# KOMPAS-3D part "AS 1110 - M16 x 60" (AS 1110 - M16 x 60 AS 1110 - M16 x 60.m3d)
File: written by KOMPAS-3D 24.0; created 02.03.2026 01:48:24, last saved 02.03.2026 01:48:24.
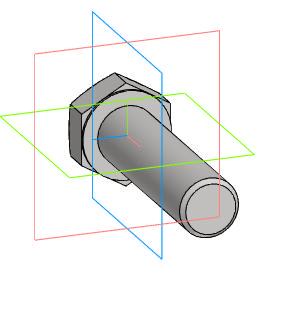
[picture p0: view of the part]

Document properties: Автор: R2D2; Полное имя файла: E:\Работа\Зайцев\GVWR3131M-2W-F-S Задвижка клиновая с выдвижным штоком DN.ru Ду50-200 Ру63\DN150\исходные материалы\AS 1110 - M16 x 60 AS 1110 - M16 x 60.m3d

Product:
- Body: Solid1  | qty 1
- Part/product: AS 1110 - M16 x 60
    Комментарий: Болты и винты   шестигранные точные   метрические ISO
    additional columns: Сталь, мягкая

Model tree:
1. Solid1  (labels: Solid1)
